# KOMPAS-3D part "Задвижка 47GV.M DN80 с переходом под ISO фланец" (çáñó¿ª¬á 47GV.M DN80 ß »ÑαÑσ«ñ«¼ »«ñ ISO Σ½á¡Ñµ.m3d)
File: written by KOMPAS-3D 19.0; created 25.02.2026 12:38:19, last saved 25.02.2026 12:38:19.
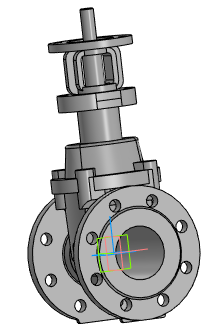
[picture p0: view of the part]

Document properties: Автор: Энергия; Полное имя файла: 47GV.M DN80\Задвижка 47GV.M DN80 с переходом под ISO фланец.a3d

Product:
- Part/product: Задвижка 47GV.M DN80 с переходом под ISO фланец
    Масса: 22.0914
  - Component: Задвижка с обрезиненным клином DN80. Сборочный чертеж  | designation DR.47GVM.080.16.00.00СБ  | pos. 0  | Масса: 15.8764; Раздел спецификации: Документация; Форматы листов документа: 2xA3; source file: 47GV.M DN80\DR.47GVM.080.16.00.000 СБ - Задвижка с обрезиненным клином DN80.cdw
- Part/product: Задвижка 47GV.M DN80 с переходом под ISO фланец  | designation 01
    Масса: 15.8677
  - Component [detail]: Стойка  | Материал: ВЧ50 ГОСТ 7293-85 (density 7200 kg/m3); Масса: 1.9123; source file: 47GV.M DN80\DR.47GVAM.100.16.00.001 - Стойка.cdw, 47GV.M DN80\Стойка DN100.m3d
  - Component [detail]: Удлинитель шпинделя  | Материал: Сталь 20Х13 ГОСТ 5632-72 (density 7670 kg/m3); Масса: 0.393756; source file: 47GV.M DN80\DR.47GVAM.100.16.00.002 - Удлинитель шпинделя.cdw, 47GV.M DN80\Удлинитель шпинделя DN100.m3d
  - Component [detail]: Крышка DN80  | pos. 4  | Материал: ВЧ50 ГОСТ 7293-85 (density 7200 kg/m3); Масса: 5.8711; Раздел спецификации: Детали; Форматы листов документа: 2xA3; source file: 47GV.M DN80\DR.47GVM.080.16.00.002 - Крышка.cdw, 47GV.M DN80\Крышка DN80.m3d
  - Component [detail]: Корпус DN80  | pos. 3  | Материал: ВЧ50 ГОСТ 7293-85 (density 7200 kg/m3); Масса: 13.7997; Раздел спецификации: Детали; Форматы листов документа: 2xA3; source file: 47GV.M DN80\DR.47GVM.050.16.00.001 - Корпус.cdw, 47GV.M DN80\DR.47GVM.080.16.00.001 - Корпус.cdw, 47GV.M DN80\Корпус DN80.m3d
  - Component [assembly]: Клин с направляющими  | designation DR.47GVM.080.16.01.000  | pos. 4  | Раздел спецификации: Сборочные единицы; Форматы листов документа: A4; source file: 47GV.M DN80\DR.47GVM.080.16.01.000 - Клин с направляющими.a3d, 47GV.M DN80\DR.47GVM.080.16.01.000 - Клин с направляющими.spw, 47GV.M DN80\DR.47GVM.080.16.01.000 СБ - Клин с направляющими.cdw
  - Component [detail]: Шпиндель  | pos. 5  | Материал: Сталь 20Х13 ГОСТ 5632 - 2014 (density 7670 kg/m3); Масса: 0.114456; Раздел спецификации: Детали; Форматы листов документа: A3; source file: 47GV.M DN80\DR.47GVM.080.16.00.003 - Шпиндель.cdw, 47GV.M DN80\Шпиндель DN80.m3d

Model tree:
1. Операция без истории:1

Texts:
  Точка начала. Х
  Точка начала. Y
  Точка начала. Z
